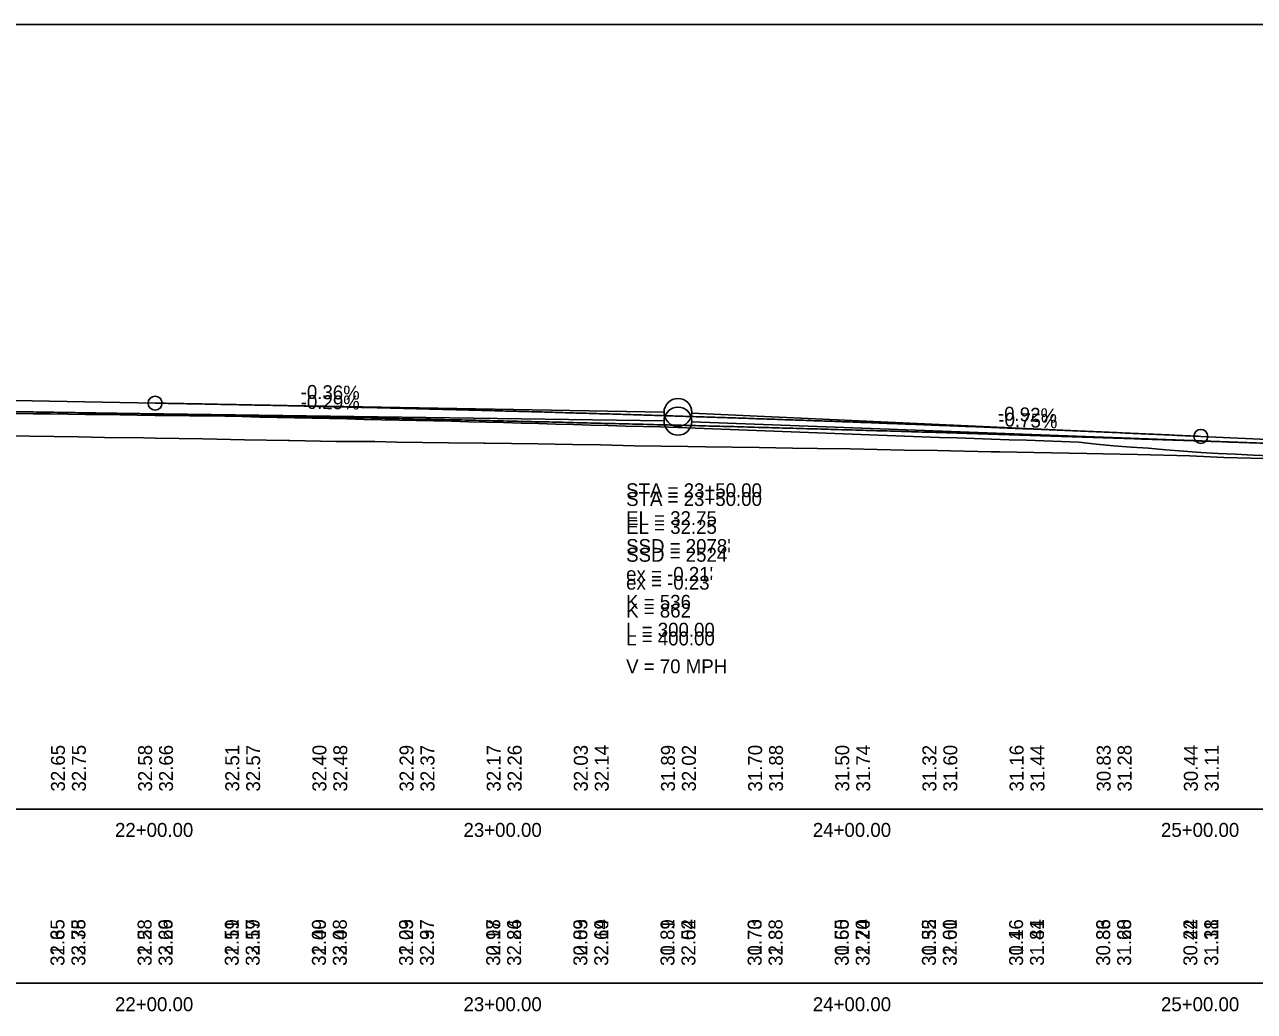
# Model space of a CAD drawing. Extents: x 3880794 to 3915434, y 287517 to 300173.
# Drawn here: x 3882700.9 to 3883053.7, y 297716.1 to 297999.2 of the extents above; entities that cross this region are included whole.
import ezdxf

# ---------------------------------------------------------------- set-up
doc = ezdxf.new("R2010")
doc.units = 0
for name, color, linetype in [('Level 1', 7, 'Continuous'), ('Level 2', 7, 'Continuous'), ('Level 30', 7, 'Continuous'), ('Level 31', 7, 'Continuous'), ('Level 32', 7, 'Continuous'), ('Level 62', 7, 'Continuous'), ('Level 63', 7, 'Continuous')]:
    doc.layers.add(name, color=color, linetype=linetype)

msp = doc.modelspace()

# ---------------------------------------------------------------- linework, layer by layer
at = {"layer": 'Level 1'}
for p, q in [((3882688.3, 297888.3), (3882884.3, 297885.5)), ((3883088.3, 297877.94), (3882892.29, 297885.29))]:
    msp.add_line(p, q, dxfattribs=at)
msp.add_lwpolyline([(3882691.39, 297881.28), (3882702.29, 297881.14), (3882716.34, 297880.91), (3882723.78, 297880.79), (3882735.12, 297880.65), (3882738.31, 297880.6), (3882751.98, 297880.35), (3882763.94, 297880.11), (3882776.44, 297879.88), (3882776.96, 297879.87), (3882790.17, 297879.6), (3882801.3, 297879.56), (3882807.64, 297879.41), (3882822.44, 297879.2), (3882832.63, 297879.16), (3882833.04, 297879.16), (3882848.06, 297878.95), (3882858.02, 297878.72), (3882866.12, 297878.61), (3882875.88, 297878.39), (3882891.17, 297878.2), (3882896.22, 297878.08), (3882911.64, 297877.89), (3882921.21, 297877.73), (3882928.3, 297877.64), (3882937.68, 297877.48), (3882953.23, 297877.14), (3882962.8, 297876.98), (3882978.16, 297876.64), (3882980.64, 297876.6), (3882990.44, 297876.46), (3883005.6, 297876.13), (3883010.32, 297876.02), (3883020.14, 297875.88), (3883035.18, 297875.45), (3883044.95, 297875.04), (3883060.37, 297874.6)], dxfattribs=at)
msp.add_circle((3882888.3, 297885.44), 4, dxfattribs=at)
msp.add_spline([(3882688.3, 297888.3), (3882696.3, 297888.18), (3882704.3, 297888.06), (3882712.3, 297887.94), (3882720.3, 297887.81), (3882728.3, 297887.68), (3882736.3, 297887.54), (3882744.3, 297887.41), (3882752.3, 297887.26), (3882760.3, 297887.12), (3882768.3, 297886.97), (3882776.3, 297886.82), (3882784.3, 297886.66), (3882792.3, 297886.5), (3882800.3, 297886.33), (3882808.3, 297886.16), (3882816.3, 297885.99), (3882824.3, 297885.82), (3882832.3, 297885.64), (3882840.3, 297885.46), (3882848.3, 297885.27), (3882856.3, 297885.08), (3882864.3, 297884.88), (3882872.3, 297884.69), (3882880.3, 297884.48), (3882888.3, 297884.28), (3882896.3, 297884.07), (3882904.3, 297883.86), (3882912.3, 297883.64), (3882920.3, 297883.42), (3882928.3, 297883.2), (3882936.3, 297882.97), (3882944.3, 297882.74), (3882952.3, 297882.5), (3882960.3, 297882.27), (3882968.3, 297882.02), (3882976.3, 297881.78), (3882984.3, 297881.53), (3882992.3, 297881.27), (3883000.3, 297881.02), (3883008.3, 297880.76), (3883016.3, 297880.49), (3883024.3, 297880.22), (3883032.3, 297879.95), (3883040.3, 297879.67), (3883048.3, 297879.39), (3883056.3, 297879.11), (3883064.3, 297878.82), (3883072.3, 297878.53), (3883080.3, 297878.24), (3883088.3, 297877.94)], degree=3, dxfattribs=at)
at = {"layer": 'Level 2'}
for p, q in [((3882688.3, 297891.51), (3882738.3, 297890.62)), ((3882738.3, 297890.62), (3882884.3, 297888.01)), ((3883038.3, 297881.07), (3882892.29, 297887.76)), ((3883038.3, 297881.07), (3883088.3, 297878.77))]:
    msp.add_line(p, q, dxfattribs=at)
for points in [[(3882698.3, 297887.65), (3882703.3, 297887.58), (3882708.3, 297887.51), (3882713.3, 297887.45), (3882718.3, 297887.38), (3882723.3, 297887.32), (3882728.3, 297887.25), (3882733.3, 297887.18), (3882738.3, 297887.11), (3882743.3, 297887.05), (3882748.3, 297886.98), (3882753.3, 297886.92), (3882758.3, 297886.85), (3882763.3, 297886.73), (3882768.3, 297886.62), (3882773.3, 297886.51), (3882778.3, 297886.4), (3882783.3, 297886.29), (3882788.3, 297886.18), (3882793.3, 297886.06), (3882798.3, 297885.95), (3882803.3, 297885.84), (3882808.3, 297885.73), (3882813.3, 297885.62), (3882818.3, 297885.51), (3882823.3, 297885.4), (3882828.3, 297885.29), (3882833.3, 297885.16), (3882838.3, 297885.02), (3882843.3, 297884.88), (3882848.3, 297884.74), (3882853.3, 297884.61), (3882858.3, 297884.47), (3882863.3, 297884.33), (3882868.3, 297884.19), (3882873.3, 297884.05), (3882878.3, 297883.91), (3882883.3, 297883.78), (3882888.3, 297883.64), (3882893.3, 297883.45), (3882898.3, 297883.25), (3882903.3, 297883.05), (3882908.3, 297882.88), (3882913.3, 297882.68), (3882918.3, 297882.48), (3882923.3, 297882.29), (3882928.3, 297882.09), (3882933.3, 297881.9), (3882938.3, 297881.71), (3882943.3, 297881.51), (3882948.3, 297881.32), (3882953.3, 297881.12), (3882958.3, 297880.93), (3882963.3, 297880.77), (3882968.3, 297880.61), (3882973.3, 297880.45), (3882978.3, 297880.29), (3882983.3, 297880.13), (3882988.3, 297879.97), (3882993.3, 297879.81), (3882998.3, 297879.65), (3883003.3, 297879.4), (3883008.3, 297878.86), (3883013.3, 297878.32), (3883018.3, 297878.01), (3883023.3, 297877.65), (3883028.3, 297877.23), (3883033.3, 297876.82), (3883038.3, 297876.41)], [(3883038.3, 297876.41), (3883043.3, 297876.16), (3883048.3, 297875.94), (3883053.3, 297875.73), (3883058.3, 297875.52)]]:
    msp.add_lwpolyline(points, dxfattribs=at)
for centre, radius in [((3882738.3, 297890.62), 2), ((3882888.3, 297887.94), 4), ((3883038.3, 297881.07), 2)]:
    msp.add_circle(centre, radius, dxfattribs=at)
msp.add_spline([(3882738.3, 297890.62), (3882744.3, 297890.51), (3882750.3, 297890.4), (3882756.3, 297890.28), (3882762.3, 297890.16), (3882768.3, 297890.04), (3882774.3, 297889.92), (3882780.3, 297889.79), (3882786.3, 297889.65), (3882792.3, 297889.52), (3882798.3, 297889.38), (3882804.3, 297889.24), (3882810.3, 297889.09), (3882816.3, 297888.94), (3882822.3, 297888.79), (3882828.3, 297888.63), (3882834.3, 297888.48), (3882840.3, 297888.31), (3882846.3, 297888.15), (3882852.3, 297887.98), (3882858.3, 297887.8), (3882864.3, 297887.63), (3882870.3, 297887.45), (3882876.3, 297887.27), (3882882.3, 297887.08), (3882888.3, 297886.89), (3882894.3, 297886.7), (3882900.3, 297886.5), (3882906.3, 297886.3), (3882912.3, 297886.1), (3882918.3, 297885.89), (3882924.3, 297885.68), (3882930.3, 297885.47), (3882936.3, 297885.26), (3882942.3, 297885.04), (3882948.3, 297884.81), (3882954.3, 297884.59), (3882960.3, 297884.36), (3882966.3, 297884.12), (3882972.3, 297883.89), (3882978.3, 297883.65), (3882984.3, 297883.41), (3882990.3, 297883.16), (3882996.3, 297882.91), (3883002.3, 297882.66), (3883008.3, 297882.4), (3883014.3, 297882.14), (3883020.3, 297881.88), (3883026.3, 297881.61), (3883032.3, 297881.34), (3883038.3, 297881.07)], degree=3, dxfattribs=at)
at = {"layer": 'Level 62'}
msp.add_lwpolyline([(3882438.3, 297774.19), (3883138.3, 297774.19), (3883138.3, 297999.19), (3882438.3, 297999.19)], close=True, dxfattribs=at)
msp.add_lwpolyline([(3882438.3, 297774.19), (3883138.3, 297774.19), (3883138.3, 297999.19), (3882438.3, 297999.19)], close=True, dxfattribs=at)
at = {"layer": 'Level 63'}
msp.add_line((3881538.3, 297724.19), (3896411.35, 297724.19), dxfattribs=at)

# ---------------------------------------------------------------- texts
at = {"layer": 'Level 2'}
for s, rotation, p in [('-0.36%', 358.977, (3882780.03, 297891.87)), ('-0.92%', 357.3758, (3882980.01, 297885.74))]:
    msp.add_text(s, height=4, rotation=rotation, dxfattribs=at).set_placement(p)
for s, p in [('STA = 23+50.00', (3882873.44, 297863.61)), ('EL = 32.75', (3882873.44, 297855.61)), ("SSD = 2078'", (3882873.44, 297847.61)), ("ex = -0.21'", (3882873.44, 297839.61)), ('K = 536', (3882873.44, 297831.61)), ('L = 300.00', (3882873.44, 297823.61))]:
    msp.add_text(s, height=4, dxfattribs=at).set_placement(p)
at = {"layer": 'Level 30'}
for s, p in [('22+00.00', (3882726.8, 297766.19)), ('22+00.00', (3882726.8, 297766.19)), ('23+00.00', (3882826.77, 297766.19)), ('23+00.00', (3882826.77, 297766.19)), ('24+00.00', (3882926.99, 297766.19)), ('24+00.00', (3882926.99, 297766.19)), ('25+00.00', (3883026.87, 297766.19)), ('25+00.00', (3883026.87, 297766.19)), ('22+00.00', (3882726.8, 297716.19)), ('22+00.00', (3882726.8, 297716.19)), ('23+00.00', (3882826.77, 297716.19)), ('23+00.00', (3882826.77, 297716.19)), ('24+00.00', (3882926.99, 297716.19)), ('24+00.00', (3882926.99, 297716.19)), ('25+00.00', (3883026.87, 297716.19)), ('25+00.00', (3883026.87, 297716.19))]:
    msp.add_text(s, height=4, dxfattribs=at).set_placement(p)
at = {"layer": 'Level 31'}
for s, rotation, p in [('-0.29%', 359.1815, (3882780.05, 297888.99)), ('-0.75%', 357.8524, (3882980.18, 297884)), ('32.75', 90, (3882718.44, 297779.19)), ('32.66', 90, (3882743.44, 297779.19)), ('32.57', 90, (3882768.44, 297779.19)), ('32.48', 90, (3882793.44, 297779.19)), ('32.37', 90, (3882818.44, 297779.19)), ('32.26', 90, (3882843.44, 297779.19)), ('32.14', 90, (3882868.44, 297779.19)), ('32.02', 90, (3882893.44, 297779.19)), ('31.88', 90, (3882918.44, 297779.19)), ('31.74', 90, (3882943.44, 297779.19)), ('31.60', 90, (3882968.44, 297779.19)), ('31.44', 90, (3882993.44, 297779.19)), ('31.28', 90, (3883018.44, 297779.19)), ('31.11', 90, (3883043.44, 297779.19)), ('31.35', 90, (3882712.3, 297729.19)), ('32.75', 90, (3882718.3, 297729.19)), ('31.28', 90, (3882737.3, 297729.19)), ('32.66', 90, (3882743.3, 297729.19)), ('31.19', 90, (3882762.3, 297729.19)), ('32.57', 90, (3882768.3, 297729.19)), ('31.09', 90, (3882787.3, 297729.19)), ('32.48', 90, (3882793.3, 297729.19)), ('31.03', 90, (3882812.3, 297729.19)), ('32.37', 90, (3882818.3, 297729.19)), ('30.98', 90, (3882837.3, 297729.19)), ('32.26', 90, (3882843.3, 297729.19)), ('30.89', 90, (3882862.3, 297729.19)), ('32.14', 90, (3882868.3, 297729.19)), ('30.81', 90, (3882887.3, 297729.19)), ('32.02', 90, (3882893.3, 297729.19)), ('30.73', 90, (3882912.3, 297729.19)), ('31.88', 90, (3882918.3, 297729.19)), ('30.65', 90, (3882937.3, 297729.19)), ('31.74', 90, (3882943.3, 297729.19)), ('30.55', 90, (3882962.3, 297729.19)), ('31.60', 90, (3882968.3, 297729.19)), ('30.46', 90, (3882987.3, 297729.19)), ('31.44', 90, (3882993.3, 297729.19)), ('30.36', 90, (3883012.3, 297729.19)), ('31.28', 90, (3883018.3, 297729.19)), ('30.22', 90, (3883037.3, 297729.19)), ('31.11', 90, (3883043.3, 297729.19))]:
    msp.add_text(s, height=4, rotation=rotation, dxfattribs=at).set_placement(p)
for s, p in [('STA = 23+50.00', (3882873.44, 297861.11)), ('EL = 32.25', (3882873.44, 297853.11)), ("SSD = 2524'", (3882873.44, 297845.11)), ("ex = -0.23'", (3882873.44, 297837.11)), ('K = 862', (3882873.44, 297829.11)), ('L = 400.00', (3882873.44, 297821.11)), ('V = 70 MPH', (3882873.44, 297813.11))]:
    msp.add_text(s, height=4, dxfattribs=at).set_placement(p)
at = {"layer": 'Level 32'}
for s, p in [('32.65', (3882712.44, 297779.19)), ('32.58', (3882737.44, 297779.19)), ('32.51', (3882762.44, 297779.19)), ('32.40', (3882787.44, 297779.19)), ('32.29', (3882812.44, 297779.19)), ('32.17', (3882837.44, 297779.19)), ('32.03', (3882862.44, 297779.19)), ('31.89', (3882887.44, 297779.19)), ('31.70', (3882912.44, 297779.19)), ('31.50', (3882937.44, 297779.19)), ('31.32', (3882962.44, 297779.19)), ('31.16', (3882987.44, 297779.19)), ('30.83', (3883012.44, 297779.19)), ('30.44', (3883037.44, 297779.19)), ('32.65', (3882712.3, 297729.19)), ('33.38', (3882718.3, 297729.19)), ('32.58', (3882737.3, 297729.19)), ('33.29', (3882743.3, 297729.19)), ('32.51', (3882762.3, 297729.19)), ('33.19', (3882768.3, 297729.19)), ('32.40', (3882787.3, 297729.19)), ('33.08', (3882793.3, 297729.19)), ('32.29', (3882812.3, 297729.19)), ('32.97', (3882818.3, 297729.19)), ('32.17', (3882837.3, 297729.19)), ('32.84', (3882843.3, 297729.19)), ('32.03', (3882862.3, 297729.19)), ('32.69', (3882868.3, 297729.19)), ('31.89', (3882887.3, 297729.19)), ('32.54', (3882893.3, 297729.19)), ('31.70', (3882912.3, 297729.19)), ('32.38', (3882918.3, 297729.19)), ('31.50', (3882937.3, 297729.19)), ('32.20', (3882943.3, 297729.19)), ('31.32', (3882962.3, 297729.19)), ('32.01', (3882968.3, 297729.19)), ('31.16', (3882987.3, 297729.19)), ('31.81', (3882993.3, 297729.19)), ('30.83', (3883012.3, 297729.19)), ('31.60', (3883018.3, 297729.19)), ('30.44', (3883037.3, 297729.19)), ('31.38', (3883043.3, 297729.19))]:
    msp.add_text(s, height=4, rotation=90, dxfattribs=at).set_placement(p)

doc.saveas('drawing.dxf')
